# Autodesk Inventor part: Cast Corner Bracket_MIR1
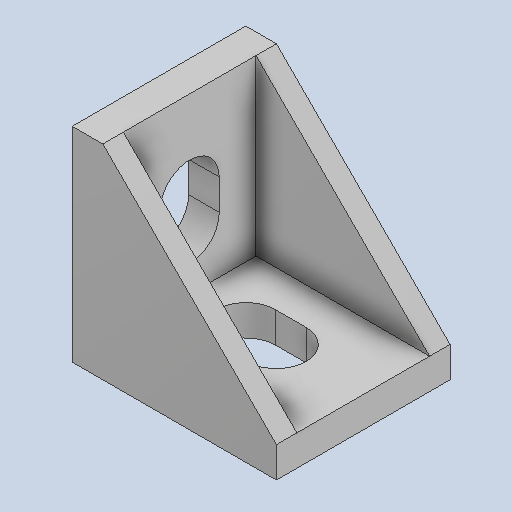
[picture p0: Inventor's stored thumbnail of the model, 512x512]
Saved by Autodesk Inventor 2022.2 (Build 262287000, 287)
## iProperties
Created: 2019-09
Part Number: Cast Corner Bracket_MIR1
Material: SolidWorks Materials|6061-T6 (SS)
Document SubType Name: Modeling
Designer: 18907419
Density: 2.7 g/cm^3
Appearance: Default
Author: 18907419
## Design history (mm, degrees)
feature "Solido1"
node "Solido2"
